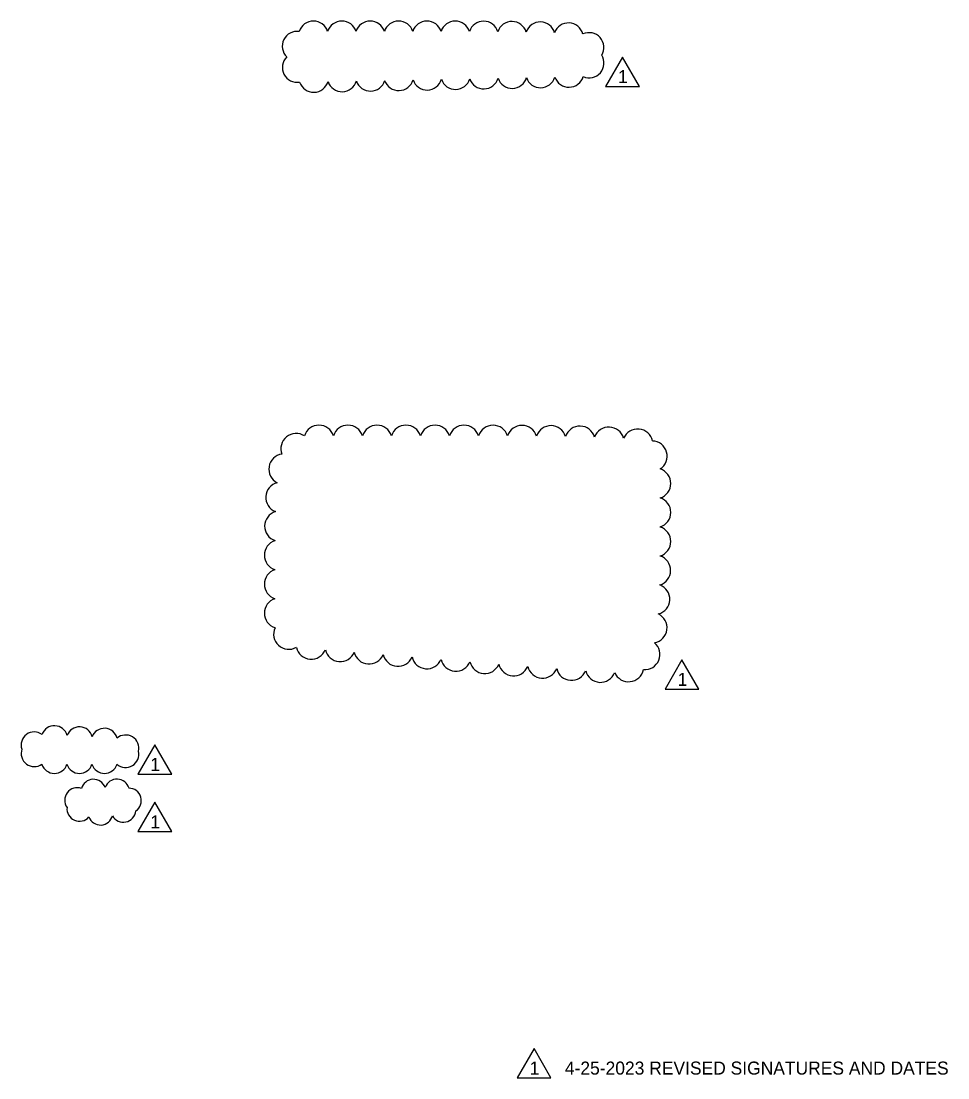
# Model space of a CAD drawing. Extents: x -10 to 89.7, y -4.8 to 22.
# Drawn here: x 46.63 to 56.58, y 0.88 to 12.23 of the extents above; entities that cross this region are included whole.
import ezdxf

# ---------------------------------------------------------------- set-up
doc = ezdxf.new("R2010")
doc.units = 0
doc.layers.add('GM_X_Minor_River_Text', color=7, linetype='Continuous')

msp = doc.modelspace()

# ---------------------------------------------------------------- linework, layer by layer
at = {"layer": 'GM_X_Minor_River_Text'}
for points in [[(53.085, 11.844), (52.903, 11.529), (53.267, 11.529)], [(53.724, 5.371), (53.542, 5.056), (53.906, 5.056)], [(48.064, 4.458), (47.882, 4.143), (48.246, 4.143)], [(48.064, 3.841), (47.882, 3.526), (48.246, 3.526)], [(52.136, 1.197), (51.954, 0.882), (52.318, 0.882)]]:
    msp.add_lwpolyline(points, close=True, dxfattribs=at)
for centre, radius, start, end in [((49.768, 12.07), 0.16, 17.5, 162.5), ((50.073, 12.07), 0.16, 17.5, 162.5), ((50.377, 12.07), 0.16, 17.5, 162.5), ((50.682, 12.07), 0.16, 17.5, 162.5), ((50.986, 12.07), 0.16, 17.5, 162.5), ((51.29, 12.07), 0.16, 17.4229, 162.4229), ((51.595, 12.069), 0.16, 17.1809, 162.1809), ((51.899, 12.066), 0.16, 16.8234, 161.8234), ((52.203, 12.061), 0.16, 16.2185, 161.2185), ((52.506, 12.05), 0.16, 14.7841, 159.7841), ((49.592, 11.961), 0.159, 81.1563, 226.1563), ((52.726, 11.946), 0.16, 329.4057, 114.4057), ((49.593, 11.732), 0.159, 134.6781, 279.6781), ((52.727, 11.781), 0.16, 246.5473, 31.5473), ((49.771, 11.626), 0.16, 198.6467, 343.6467), ((50.076, 11.632), 0.16, 198.6467, 343.6467), ((50.38, 11.638), 0.16, 198.6467, 343.6467), ((50.684, 11.644), 0.16, 198.6467, 343.6467), ((50.989, 11.65), 0.16, 198.6467, 343.6467), ((51.293, 11.656), 0.16, 198.6424, 343.6424), ((51.597, 11.662), 0.16, 198.6336, 343.6336), ((51.902, 11.668), 0.16, 198.6204, 343.6204), ((52.206, 11.674), 0.16, 198.5973, 343.5973), ((52.511, 11.68), 0.16, 198.5369, 343.5369), ((49.827, 7.728), 0.163, 17.5, 162.5), ((50.138, 7.728), 0.163, 17.5, 162.5), ((50.45, 7.728), 0.163, 17.5, 162.5), ((50.761, 7.728), 0.163, 17.5, 162.5), ((51.073, 7.728), 0.163, 17.5, 162.5), ((51.384, 7.728), 0.163, 17.5, 162.5), ((51.696, 7.727), 0.163, 17.4427, 162.4427), ((52.007, 7.726), 0.163, 17.1731, 162.1731), ((52.318, 7.723), 0.163, 16.7855, 161.7855), ((52.629, 7.718), 0.163, 16.199, 161.199), ((52.94, 7.708), 0.163, 15.1472, 160.1472), ((53.248, 7.687), 0.163, 12.0783, 157.0783), ((49.581, 7.64), 0.163, 56.495, 201.495), ((53.402, 7.558), 0.163, 302.8184, 87.8184), ((49.452, 7.419), 0.163, 98.3226, 243.3226), ((53.441, 7.265), 0.163, 287.5, 72.5), ((49.419, 7.115), 0.163, 104.024, 249.024), ((53.441, 6.954), 0.163, 287.5, 72.5), ((49.407, 6.806), 0.163, 106.6116, 251.6116), ((53.441, 6.642), 0.163, 287.5, 72.5), ((49.404, 6.495), 0.163, 107.5, 252.5), ((53.439, 6.331), 0.163, 286.9445, 71.9445), ((49.404, 6.183), 0.163, 107.5, 252.5), ((53.43, 6.022), 0.163, 284.5086, 69.5086), ((49.404, 5.872), 0.163, 107.5, 252.5), ((53.401, 5.716), 0.163, 279.8608, 64.8608), ((49.503, 5.647), 0.163, 154.9715, 299.9715), ((49.744, 5.541), 0.163, 192.7323, 337.7323), ((50.055, 5.515), 0.163, 192.7323, 337.7323), ((50.365, 5.489), 0.163, 192.7323, 337.7323), ((53.325, 5.429), 0.163, 265.1546, 50.1546), ((50.676, 5.464), 0.163, 192.7323, 337.7323), ((50.986, 5.438), 0.163, 192.7323, 337.7323), ((51.297, 5.412), 0.163, 192.7628, 337.7628), ((51.607, 5.386), 0.163, 192.8413, 337.8413), ((51.917, 5.361), 0.163, 192.9458, 337.9458), ((52.228, 5.337), 0.163, 193.0948, 338.0948), ((52.538, 5.314), 0.163, 193.3331, 338.3331), ((52.849, 5.292), 0.163, 193.8179, 338.8179), ((53.151, 5.299), 0.163, 203.6378, 348.6378), ((46.987, 4.522), 0.141, 15.0899, 160.0899), ((46.771, 4.456), 0.141, 53.6468, 198.6468), ((47.256, 4.51), 0.141, 14.7595, 159.7595), ((47.523, 4.495), 0.141, 13.9782, 158.9782), ((47.752, 4.423), 0.141, 345.9864, 130.9864), ((46.771, 4.365), 0.141, 160.597, 305.597), ((47.752, 4.356), 0.141, 228.551, 13.551), ((46.987, 4.292), 0.141, 197.5, 342.5), ((47.256, 4.292), 0.141, 197.5, 342.5), ((47.525, 4.292), 0.141, 197.5, 342.5), ((47.407, 3.954), 0.134, 19.9654, 164.9654), ((47.659, 3.956), 0.134, 15.7453, 160.7453), ((47.232, 3.863), 0.134, 70.1182, 215.1182), ((47.786, 3.859), 0.134, 304.294, 89.294), ((47.256, 3.772), 0.134, 173.8075, 318.8075), ((47.728, 3.762), 0.134, 208.9979, 353.9979), ((47.482, 3.731), 0.134, 200.5335, 345.5335)]:
    msp.add_arc(centre, radius, start, end, dxfattribs=at)

# ---------------------------------------------------------------- texts
for s, p in [('1', (53.038, 11.564)), ('1', (53.677, 5.091)), ('1', (48.017, 4.178)), ('1', (48.017, 3.561)), ('1', (52.089, 0.917)), ('4-25-2023 REVISED SIGNATURES AND DATES', (52.467, 0.917))]:
    msp.add_text(s, height=0.14, dxfattribs=at).set_placement(p)

doc.saveas('drawing.dxf')
